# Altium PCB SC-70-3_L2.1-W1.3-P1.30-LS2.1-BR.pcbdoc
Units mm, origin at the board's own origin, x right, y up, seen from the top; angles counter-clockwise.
Board outline 15.15 x 14.85 mm, 2 copper layers (Top Layer, Bottom Layer), stack 0 mm thick; 1 components, 0 nets, 3 pads, 0 vias.
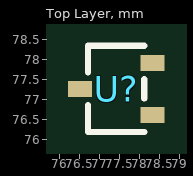
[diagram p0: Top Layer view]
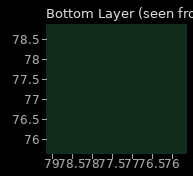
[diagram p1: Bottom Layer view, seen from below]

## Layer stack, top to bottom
Top Layer: signal copper (thickness not stored)
Bottom Layer: signal copper (thickness not stored)

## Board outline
85.003,69.85 69.85,69.85 69.85,84.702 85.003,84.702

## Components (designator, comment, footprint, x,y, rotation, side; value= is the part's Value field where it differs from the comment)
U? "" SC-70-3_L2.1-W1.3-P1.30-LS2.1-BR 77.41,77.276 r0 top

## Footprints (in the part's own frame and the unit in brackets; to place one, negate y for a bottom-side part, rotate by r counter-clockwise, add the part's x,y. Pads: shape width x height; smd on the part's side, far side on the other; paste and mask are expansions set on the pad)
SC-70-3_L2.1-W1.3-P1.30-LS2.1-BR [mm]
  rect 0.6x0.4 smd: 1(0.91,-0.65) 2(0.91,0.65) 3(-0.91,0)
  silkscreen extent -0.7,-1.08 0.7,1.08

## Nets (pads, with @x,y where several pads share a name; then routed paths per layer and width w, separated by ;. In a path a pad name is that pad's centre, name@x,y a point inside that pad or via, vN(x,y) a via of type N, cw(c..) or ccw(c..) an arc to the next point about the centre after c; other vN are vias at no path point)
pads on no net: U?.1 U?.2 U?.3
